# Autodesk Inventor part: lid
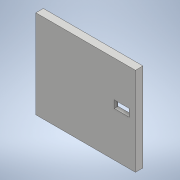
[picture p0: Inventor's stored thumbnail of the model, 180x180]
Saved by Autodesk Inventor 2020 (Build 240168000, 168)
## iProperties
Created: 2022-05
Part Number: lid
Material: Generic
Document SubType Name: Modeling
Designer: xmls36
Density: 1 g/cm^3
Appearance: Default
Author: xmls36
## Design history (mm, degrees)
sketch "Sketch1"
  geometry: L1 (0, 0)-(79.8, 0); L2 (79.8, 0)-(79.8, -70.8); L3 (79.8, -70.8)-(0, -70.8); L4 (0, -70.8)-(0, 0)
  constraints: 8 end point, 2 parallel, 1 horizontal, 1 perpendicular
  dimensions: "d0" = 70.8 distance of L1.end L2.end; "d1" = 79.8 distance of L2.end L3.end
extrude "Extrusion1" new body sketch "Sketch1" distance "d2" = 7; taper "d3" = 0 deg
sketch "Sketch2"
  geometry: L1 (-3, 3)-(-76.8, 3); L2 (-76.8, 3)-(-76.8, 67.8); L3 (-76.8, 67.8)-(-3, 67.8); L4 (-3, 67.8)-(-3, 3); L5 (0, 0)-(0, 70.8) reference; L6 (0, 70.8)-(-79.8, 70.8) reference; L7 (-79.8, 70.8)-(-79.8, 0) reference; L8 (-79.8, 0)-(0, 0) reference
  constraints: 8 end point, 2 parallel, 1 horizontal, 1 perpendicular
  dimensions: "d4" = 3 distance between parallel lines of L5 L4; "d5" = 3 distance between parallel lines of L6 L3; "d6" = 3 distance between parallel lines of L7 L2; "d7" = 3 distance between parallel lines of L8 L1
extrude "Extrusion2" cut sketch "Sketch2" distance "d8" = 4; taper "d9" = 0 deg
sketch "Sketch3"
  geometry: L1 (-5, -29)-(-17, -29); L2 (-17, -29)-(-17, -35); L3 (-17, -35)-(-5, -35); L4 (-5, -35)-(-5, -29); L5 (0, 0)-(0, -70.8) reference; L6 (-79.8, 0)-(0, 0) reference
  constraints: 8 end point, 2 parallel, 1 horizontal, 1 perpendicular
  dimensions: "d10" = 5 distance between parallel lines of L5 L4; "d11" = 6 distance of L3.end L1.start; "d12" = 12 distance of L2.end L3.end; "d13" = 29 distance between parallel lines of L6 L1
extrude "Extrusion3" cut sketch "Sketch3" distance "d14" = 3; taper "d15" = 0 deg
chamfer "Chamfer6" distance "d31" = 1; stored, may be unused: second distance "d32" = 2, angle "d33" = 45 deg
chamfer "Chamfer7" distance "d34" = 1; stored, may be unused: second distance "d35" = 2, angle "d36" = 45 deg
chamfer "Chamfer8" distance "d37" = 1; stored, may be unused: second distance "d38" = 2, angle "d39" = 45 deg
chamfer "Chamfer9" distance "d40" = 1; stored, may be unused: second distance "d41" = 2, angle "d42" = 45 deg
body "Solid1"
